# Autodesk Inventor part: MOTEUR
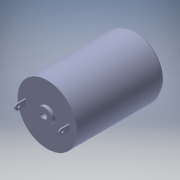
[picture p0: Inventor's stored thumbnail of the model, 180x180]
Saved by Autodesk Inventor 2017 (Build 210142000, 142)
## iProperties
Created: 2013-10
Part Number: MOTEUR
Material: Générique
Document SubType Name: Modeling
Designer: Bruno
Density: 1 g/cm^3
Appearance: Par défaut
Sending System: SolidWorks 2013
Last Author: christophe
Last Saved: 2014-02-15
Author: Bruno
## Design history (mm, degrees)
feature "Enlèv. mat.-Extru.3"
sketch "Esquisse1"
  geometry: C1 r 1.6 at (-1.166, -0.111) reference; 1 further point
extrude "Extrusion1" cut sketch "Esquisse1" distance "d0" = 10; taper "d1" = 0 deg
node "Solide1"
node "Référence1"
